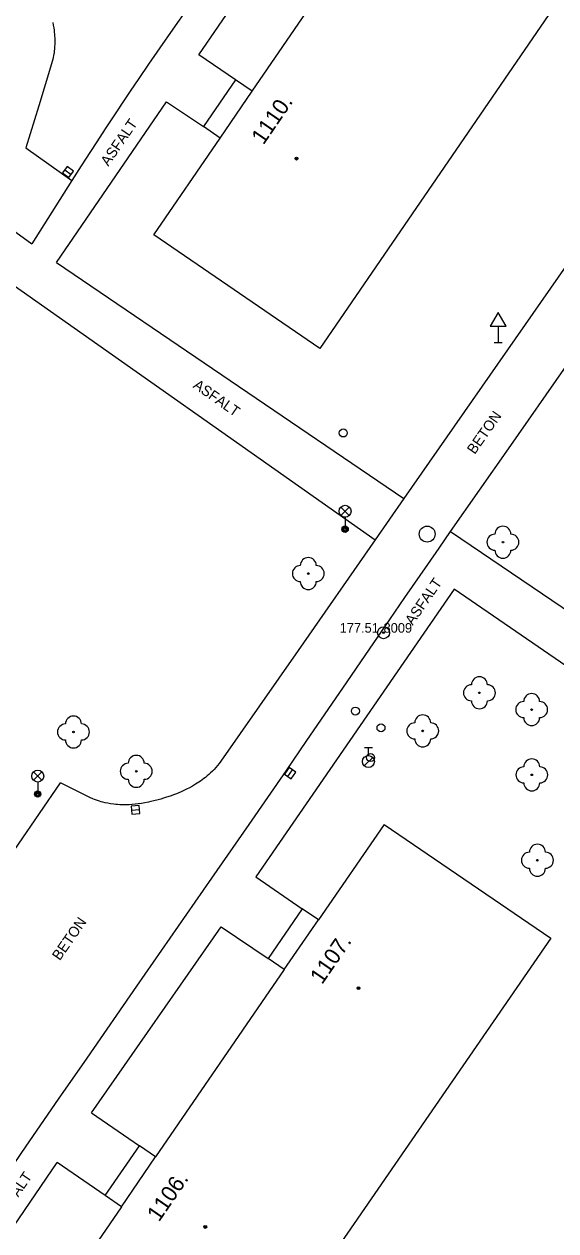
# Model space of a CAD drawing. Extents: x -539515 to -538098, y -1182060 to -1180157.
# Drawn here: x -538886.7 to -538853.4, y -1181299.9 to -1181224.5 of the extents above; entities that cross this region are included whole.
import ezdxf

# ---------------------------------------------------------------- set-up
doc = ezdxf.new("R2010")
doc.units = 0
for name, color, linetype in [('Vrstva 10', 7, 'Continuous'), ('Vrstva 11', 7, 'Continuous'), ('Vrstva 21', 7, 'Continuous'), ('Vrstva 22', 7, 'Continuous'), ('Vrstva 23', 7, 'Continuous'), ('Vrstva 27', 7, 'Continuous'), ('Vrstva 28', 7, 'Continuous'), ('Vrstva 31', 7, 'Continuous'), ('Vrstva 33', 7, 'Continuous'), ('Vrstva 34', 7, 'Continuous'), ('Vrstva 39', 7, 'Continuous'), ('Vrstva 40', 7, 'Continuous'), ('Vrstva 47', 7, 'Continuous'), ('Vrstva 5', 7, 'Continuous')]:
    doc.layers.add(name, color=color, linetype=linetype)

msp = doc.modelspace()

# ---------------------------------------------------------------- linework, layer by layer
at = {"layer": 'Vrstva 10'}
for p, q in [((-538852.117, -1181238.682), (-538857.505, -1181246.4)), ((-538856.345, -1181251.018), (-538852.73, -1181245.845)), ((-538857.505, -1181246.4), (-538862.89, -1181254.12)), ((-538859.96, -1181256.19), (-538856.345, -1181251.018)), ((-538864.69, -1181256.7), (-538869.514, -1181263.62)), ((-538869.514, -1181263.62), (-538874.34, -1181270.54)), ((-538892.84, -1181284.195), (-538884.38, -1181271.91)), ((-538879.597, -1181284.617), (-538874.915, -1181277.871)), ((-538882.717, -1181289.115), (-538879.597, -1181284.617)), ((-538884.498, -1181291.687), (-538882.717, -1181289.115))]:
    msp.add_line(p, q, dxfattribs=at)
for points in [[(-538872.711, -1181218.197), (-538874.12, -1181220.173), (-538875.348, -1181221.906), (-538876.418, -1181223.425), (-538877.349, -1181224.758), (-538878.159, -1181225.927)], [(-538884.863, -1181224.357), (-538884.832, -1181224.522), (-538884.807, -1181224.677), (-538884.787, -1181224.823), (-538884.771, -1181224.959), (-538884.759, -1181225.087), (-538884.751, -1181225.207), (-538884.745, -1181225.319), (-538884.741, -1181225.528), (-538884.743, -1181225.71), (-538884.75, -1181225.869), (-538884.761, -1181226.006), (-538884.773, -1181226.126), (-538884.786, -1181226.23), (-538884.814, -1181226.411), (-538884.839, -1181226.546), (-538884.861, -1181226.645)], [(-538878.159, -1181225.927), (-538878.864, -1181226.952), (-538879.478, -1181227.852), (-538880.013, -1181228.641), (-538880.478, -1181229.332), (-538880.884, -1181229.939), (-538881.589, -1181231.003), (-538882.115, -1181231.804), (-538882.507, -1181232.406), (-538883.091, -1181233.311), (-538883.67, -1181234.22)], [(-538884.861, -1181226.645), (-538884.898, -1181226.794), (-538884.94, -1181226.94), (-538885.745, -1181229.56), (-538886.55, -1181232.18)], [(-538883.67, -1181234.22), (-538884.925, -1181236.2), (-538886.18, -1181238.18)], [(-538862.89, -1181254.12), (-538863.79, -1181255.41), (-538864.69, -1181256.7)], [(-538863.768, -1181261.692), (-538862.82, -1181260.314), (-538861.393, -1181258.25), (-538860.678, -1181257.219), (-538859.96, -1181256.19)], [(-538870.24, -1181271.12), (-538868.954, -1181269.254), (-538866.711, -1181265.984), (-538865.03, -1181263.531), (-538863.768, -1181261.692)], [(-538874.34, -1181270.54), (-538874.444, -1181270.682), (-538874.55, -1181270.816), (-538874.658, -1181270.942), (-538874.766, -1181271.061), (-538874.875, -1181271.172), (-538874.985, -1181271.277), (-538875.094, -1181271.376), (-538875.202, -1181271.469), (-538875.31, -1181271.557), (-538875.417, -1181271.639), (-538875.523, -1181271.717), (-538875.627, -1181271.791), (-538875.729, -1181271.86), (-538875.83, -1181271.926), (-538875.929, -1181271.988), (-538876.125, -1181272.103), (-538876.312, -1181272.206), (-538876.49, -1181272.298), (-538876.66, -1181272.381), (-538876.821, -1181272.455), (-538876.974, -1181272.521), (-538877.118, -1181272.58), (-538877.254, -1181272.634), (-538877.511, -1181272.728), (-538877.737, -1181272.805), (-538877.936, -1181272.867), (-538878.111, -1181272.919), (-538878.263, -1181272.961), (-538878.53, -1181273.029), (-538878.729, -1181273.075), (-538878.878, -1181273.107), (-538879.1, -1181273.151), (-538879.32, -1181273.19), (-538879.524, -1181273.221), (-538879.718, -1181273.243), (-538879.902, -1181273.259), (-538880.076, -1181273.269), (-538880.24, -1181273.274), (-538880.395, -1181273.275), (-538880.54, -1181273.272), (-538880.677, -1181273.266), (-538880.805, -1181273.258), (-538880.925, -1181273.248), (-538881.037, -1181273.236), (-538881.246, -1181273.208), (-538881.428, -1181273.177), (-538881.586, -1181273.145), (-538881.723, -1181273.112), (-538881.842, -1181273.081), (-538881.945, -1181273.052), (-538882.124, -1181272.994), (-538882.255, -1181272.947), (-538882.353, -1181272.909), (-538882.496, -1181272.847), (-538882.637, -1181272.78)], [(-538874.915, -1181277.871), (-538872.576, -1181274.497), (-538870.24, -1181271.12)], [(-538882.637, -1181272.78), (-538883.508, -1181272.345), (-538884.38, -1181271.91)], [(-538890.08, -1181299.79), (-538888.847, -1181297.993), (-538886.53, -1181294.628), (-538884.498, -1181291.687)]]:
    msp.add_lwpolyline(points, dxfattribs=at)
at = {"layer": 'Vrstva 11'}
for p, q in [((-538875.72, -1181226.36), (-538867.52, -1181214.36)), ((-538873.425, -1181227.931), (-538875.72, -1181226.36)), ((-538884.64, -1181239.35), (-538877.74, -1181229.3)), ((-538877.74, -1181229.3), (-538875.43, -1181230.86)), ((-538902.52, -1181230.08), (-538864.69, -1181256.7)), ((-538886.55, -1181232.18), (-538883.67, -1181234.22)), ((-538891.622, -1181234.266), (-538886.18, -1181238.18)), ((-538884.64, -1181239.35), (-538862.89, -1181254.12)), ((-538859.96, -1181256.19), (-538849.272, -1181263.431)), ((-538859.73, -1181259.79), (-538872.16, -1181277.78)), ((-538830.3, -1181280.04), (-538859.73, -1181259.79)), ((-538872.16, -1181277.78), (-538869.256, -1181279.776)), ((-538882.44, -1181292.54), (-538874.32, -1181280.91)), ((-538874.32, -1181280.91), (-538871.39, -1181282.88)), ((-538882.44, -1181292.54), (-538879.446, -1181294.598)), ((-538892.89, -1181307.75), (-538884.58, -1181295.65)), ((-538881.585, -1181297.709), (-538884.58, -1181295.65))]:
    msp.add_line(p, q, dxfattribs=at)
at = {"layer": 'Vrstva 21'}
for radius in [0.375, 0.05]:
    msp.add_circle((-538864.16, -1181262.51), radius, dxfattribs=at)
at = {"layer": 'Vrstva 22'}
for centre in [(-538856.69, -1181256.85), (-538868.87, -1181258.81), (-538858.16, -1181266.27), (-538854.89, -1181267.32), (-538883.57, -1181268.72), (-538861.71, -1181268.65), (-538879.64, -1181271.18), (-538854.88, -1181271.4), (-538854.53, -1181276.74)]:
    msp.add_circle(centre, 0.05, dxfattribs=at)
for centre, start, end in [((-538857.19, -1181256.85), 90, 270), ((-538856.69, -1181256.35), 0, 180), ((-538856.19, -1181256.85), 270, 90), ((-538868.87, -1181258.31), 0, 180), ((-538856.69, -1181257.35), 180, 0), ((-538869.37, -1181258.81), 90, 270), ((-538868.37, -1181258.81), 270, 90), ((-538868.87, -1181259.31), 180, 0), ((-538858.16, -1181265.77), 0, 180), ((-538858.66, -1181266.27), 90, 270), ((-538857.66, -1181266.27), 270, 90), ((-538858.16, -1181266.77), 180, 0), ((-538855.39, -1181267.32), 90, 270), ((-538854.89, -1181266.82), 0, 180), ((-538854.39, -1181267.32), 270, 90), ((-538883.57, -1181268.22), 0, 180), ((-538861.71, -1181268.15), 0, 180), ((-538884.07, -1181268.72), 90, 270), ((-538883.07, -1181268.72), 270, 90), ((-538862.21, -1181268.65), 90, 270), ((-538861.21, -1181268.65), 270, 90), ((-538854.89, -1181267.82), 180, 0), ((-538883.57, -1181269.22), 180, 0), ((-538861.71, -1181269.15), 180, 0), ((-538880.14, -1181271.18), 90, 270), ((-538879.64, -1181270.68), 0, 180), ((-538879.14, -1181271.18), 270, 90), ((-538854.88, -1181270.9), 0, 180), ((-538855.38, -1181271.4), 90, 270), ((-538854.38, -1181271.4), 270, 90), ((-538879.64, -1181271.68), 180, 0), ((-538854.88, -1181271.9), 180, 0), ((-538854.53, -1181276.24), 0, 180), ((-538855.03, -1181276.74), 90, 270), ((-538854.03, -1181276.74), 270, 90), ((-538854.53, -1181277.24), 180, 0)]:
    msp.add_arc(centre, 0.5, start, end, dxfattribs=at)
at = {"layer": 'Vrstva 27'}
for p, q in [((-538884.114, -1181233.555), (-538883.706, -1181233.845)), ((-538870.146, -1181271.504), (-538869.862, -1181271.092)), ((-538879.939, -1181273.612), (-538879.441, -1181273.568))]:
    msp.add_line(p, q, dxfattribs=at)
for points in [[(-538884.259, -1181233.76), (-538883.85, -1181234.049), (-538883.561, -1181233.64), (-538883.97, -1181233.351)], [(-538869.94, -1181271.646), (-538869.656, -1181271.234), (-538870.068, -1181270.95), (-538870.352, -1181271.362)], [(-538879.917, -1181273.861), (-538879.419, -1181273.817), (-538879.463, -1181273.319), (-538879.961, -1181273.363)]]:
    msp.add_lwpolyline(points, close=True, dxfattribs=at)
msp.add_circle((-538861.43, -1181256.34), 0.5, dxfattribs=at)
at = {"layer": 'Vrstva 28'}
for p, q in [((-538865.36, -1181269.695), (-538864.86, -1181269.695)), ((-538865.11, -1181270.195), (-538865.11, -1181269.695)), ((-538865.368, -1181270.842), (-538864.838, -1181270.312))]:
    msp.add_line(p, q, dxfattribs=at)
for centre, radius in [((-538865.92, -1181267.41), 0.25), ((-538865.11, -1181270.57), 0.375), ((-538864.97, -1181270.32), 0.25)]:
    msp.add_circle(centre, radius, dxfattribs=at)
at = {"layer": 'Vrstva 31'}
for centre in [(-538866.68, -1181250.02), (-538864.32, -1181268.46)]:
    msp.add_circle(centre, 0.25, dxfattribs=at)
at = {"layer": 'Vrstva 33'}
for p, q in [((-538866.835, -1181255.18), (-538866.305, -1181254.65)), ((-538866.835, -1181254.65), (-538866.305, -1181255.18)), ((-538866.57, -1181255.29), (-538866.57, -1181256.04)), ((-538886.075, -1181271.74), (-538885.545, -1181271.21)), ((-538886.075, -1181271.21), (-538885.545, -1181271.74)), ((-538885.81, -1181271.85), (-538885.81, -1181272.6))]:
    msp.add_line(p, q, dxfattribs=at)
for centre, radius in [((-538866.57, -1181254.915), 0.375), ((-538866.57, -1181256.04), 0.2), ((-538866.57, -1181256.04), 0.145), ((-538866.57, -1181256.04), 0.0876), ((-538885.81, -1181271.475), 0.375), ((-538885.81, -1181272.6), 0.2), ((-538885.81, -1181272.6), 0.145), ((-538885.81, -1181272.6), 0.0876)]:
    msp.add_circle(centre, radius, dxfattribs=at)
at = {"layer": 'Vrstva 34'}
for p, q in [((-538856.98, -1181243.342), (-538856.98, -1181244.36)), ((-538857.23, -1181244.36), (-538856.73, -1181244.36))]:
    msp.add_line(p, q, dxfattribs=at)
msp.add_lwpolyline([(-538857.48, -1181243.342), (-538856.48, -1181243.342), (-538856.98, -1181242.476)], close=True, dxfattribs=at)
at = {"layer": 'Vrstva 39'}
for centre, radius in [((-538869.612, -1181232.86), 0.09), ((-538869.612, -1181232.86), 0.0398), ((-538865.726, -1181284.744), 0.09), ((-538865.726, -1181284.744), 0.0398), ((-538875.317, -1181299.672), 0.09), ((-538875.317, -1181299.672), 0.0398)]:
    msp.add_circle(centre, radius, dxfattribs=at)
at = {"layer": 'Vrstva 5'}
for p, q in [((-538837.41, -1181199.92), (-538868.14, -1181244.73)), ((-538873.425, -1181227.931), (-538875.43, -1181230.86)), ((-538872.38, -1181228.646), (-538873.425, -1181227.931)), ((-538874.385, -1181231.575), (-538875.43, -1181230.86)), ((-538868.14, -1181244.73), (-538878.53, -1181237.63)), ((-538864.13, -1181274.5), (-538868.238, -1181280.476)), ((-538864.13, -1181274.5), (-538853.7, -1181281.61)), ((-538869.256, -1181279.776), (-538871.39, -1181282.88)), ((-538868.238, -1181280.476), (-538869.256, -1181279.776)), ((-538870.373, -1181283.58), (-538868.238, -1181280.476)), ((-538853.7, -1181281.61), (-538894.91, -1181341.37)), ((-538870.373, -1181283.58), (-538878.429, -1181295.298)), ((-538870.373, -1181283.58), (-538871.39, -1181282.88)), ((-538881.585, -1181297.709), (-538879.446, -1181294.598)), ((-538878.429, -1181295.298), (-538879.446, -1181294.598)), ((-538880.567, -1181298.409), (-538878.429, -1181295.298)), ((-538880.567, -1181298.409), (-538881.585, -1181297.709)), ((-538880.567, -1181298.409), (-538888.883, -1181310.505))]:
    msp.add_line(p, q, dxfattribs=at)
for points in [[(-538872.38, -1181228.646), (-538864.214, -1181216.716)], [(-538874.385, -1181231.575), (-538872.38, -1181228.646)], [(-538878.53, -1181237.63), (-538874.385, -1181231.575)]]:
    msp.add_lwpolyline(points, dxfattribs=at)

# ---------------------------------------------------------------- texts
at = {"layer": 'Vrstva 22'}
msp.add_text('177.51 ', height=0.6, dxfattribs=at).set_placement((-538866.909, -1181262.51))
at = {"layer": 'Vrstva 23'}
msp.add_text('8009', height=0.6, dxfattribs=at).set_placement((-538864.16, -1181262.51))
at = {"layer": 'Vrstva 40'}
for s, rotation, p in [('ASFALT', 55.52779, (-538881.388, -1181233.378)), ('ASFALT', 324.86693, (-538876.13, -1181247.149)), ('BETON', 55.05075, (-538858.454, -1181251.399)), ('ASFALT', 55.35788, (-538862.335, -1181262.088)), ('BETON', 55.23392, (-538884.427, -1181283.058)), ('ASFALT', 55.51962, (-538887.986, -1181299.233))]:
    msp.add_text(s, height=0.65, rotation=rotation, dxfattribs=at).set_placement(p)
at = {"layer": 'Vrstva 47'}
for s, rotation, p in [('1110.', 55.60821, (-538871.679, -1181232.047)), ('1107.', 55.47894, (-538868.011, -1181284.557)), ('1106.', 55.50164, (-538878.218, -1181299.406))]:
    msp.add_text(s, height=1, rotation=rotation, dxfattribs=at).set_placement(p)

doc.saveas('drawing.dxf')
